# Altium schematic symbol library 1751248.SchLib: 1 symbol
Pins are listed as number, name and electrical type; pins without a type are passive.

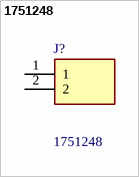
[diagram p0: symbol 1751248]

## 1751248
designator J?
PCB terminal block, 3.5mm pitch, 2 way Phoenix Contact COMBICON MKDS Series 3.5mm Pitch Straight PCB Terminal Block with Screw Termination, Through Hole; Geometry.Height: 8.65mm
footprint 1751248
pins: 1, 2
